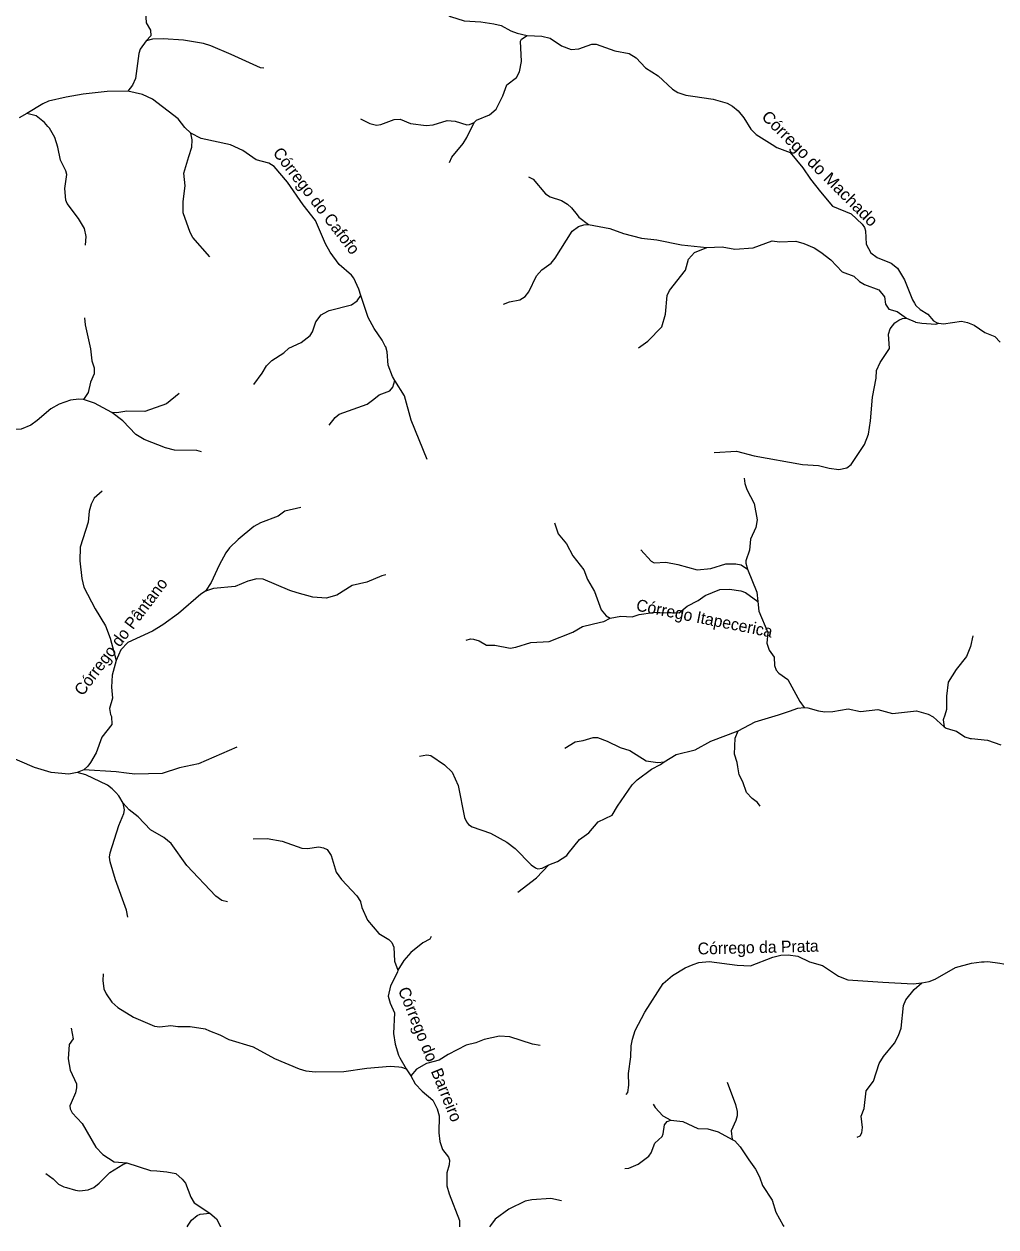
# Model space of a CAD drawing. Extents: x 473.9 to 500, y 7733.1 to 7760.8.
# Drawn here: x 480.86 to 487.45, y 7733.14 to 7741.31 of the extents above; entities that cross this region are included whole.
import ezdxf
from ezdxf.enums import TextEntityAlignment as Align

# ---------------------------------------------------------------- set-up
doc = ezdxf.new("R2010")
doc.units = 0
doc.header["$LTSCALE"] = 0.032
doc.layers.add('61', color=7, linetype='Continuous')
doc.layers.add('7', color=7, linetype='Continuous', lineweight=25)

msp = doc.modelspace()

# ---------------------------------------------------------------- linework, layer by layer
at = {"layer": '7'}
for p, q in [((480.8795, 7740.7), (480.8283, 7740.6712)), ((481.2664, 7736.2474), (481.2199, 7736.2289)), ((483.4526, 7734.2176), (483.4832, 7734.1696))]:
    msp.add_line(p, q, dxfattribs=at)
for points in [[(482.1099, 7741.7153), (481.984, 7741.7217), (481.7828, 7741.6667), (481.7217, 7741.6213), (481.6941, 7741.5852), (481.6778, 7741.5085), (481.6894, 7741.3158), (481.7178, 7741.266), (481.7194, 7741.228), (481.6886, 7741.1924)], [(482.7052, 7741.7027), (482.7719, 7741.7088), (482.8259, 7741.7005), (482.8866, 7741.6633), (482.9371, 7741.6172), (482.9774, 7741.6102), (483.0334, 7741.615), (483.0776, 7741.6118), (483.1055, 7741.6026), (483.2118, 7741.5318), (483.3296, 7741.4866), (483.4169, 7741.466), (483.5224, 7741.4723), (483.5616, 7741.4644), (483.6052, 7741.4474), (483.7526, 7741.3582), (483.8467, 7741.3279), (483.9579, 7741.3224), (484.0477, 7741.3087), (484.0961, 7741.2966), (484.1635, 7741.2601), (484.2055, 7741.2445), (484.2731, 7741.2289)], [(482.4876, 7741.0084), (482.4636, 7741.0099), (482.2663, 7741.1003), (482.1274, 7741.1594), (482.0783, 7741.1741), (481.941, 7741.1981), (481.805, 7741.2077), (481.7325, 7741.2046), (481.6886, 7741.1924)], [(483.9144, 7740.64), (483.9284, 7740.6552), (484.0168, 7740.6916), (484.062, 7740.7305), (484.1079, 7740.8197), (484.1358, 7740.8951), (484.2019, 7740.9445), (484.221, 7740.9835), (484.2337, 7741.0519), (484.2291, 7741.1908), (484.2343, 7741.204), (484.2731, 7741.2289)], [(484.2731, 7741.2289), (484.3717, 7741.2253), (484.4281, 7741.2108), (484.5059, 7741.1595), (484.5708, 7741.1347), (484.624, 7741.1386), (484.6806, 7741.1589), (484.7116, 7741.17), (484.7408, 7741.1708), (484.8676, 7741.1251), (484.9651, 7741.1072), (485.0115, 7741.0778), (485.0756, 7741.0091), (485.1609, 7740.9556), (485.2587, 7740.8657), (485.2956, 7740.842), (485.3486, 7740.825), (485.3963, 7740.8181), (485.5358, 7740.798), (485.6292, 7740.7706), (485.6666, 7740.7488), (485.7035, 7740.7184), (485.7432, 7740.6714), (485.7911, 7740.5939), (485.8265, 7740.5581), (485.9346, 7740.4899), (485.966, 7740.47), (486.058, 7740.4362), (486.1442, 7740.332), (486.1941, 7740.2536), (486.2639, 7740.1693), (486.345, 7740.0714), (486.4707, 7740.0195), (486.5467, 7739.95), (486.5622, 7739.9262), (486.5673, 7739.9032), (486.5718, 7739.8126), (486.6049, 7739.7556), (486.6485, 7739.7221), (486.7433, 7739.6851), (486.7864, 7739.6516), (486.8333, 7739.5702), (486.887, 7739.4355), (486.9016, 7739.4121), (486.9104, 7739.398), (486.9394, 7739.3699), (486.9903, 7739.338), (487.0298, 7739.2941), (487.0546, 7739.2788), (487.0664, 7739.277)], [(481.6886, 7741.1924), (481.649, 7741.1375), (481.6399, 7741.1076), (481.6155, 7740.9364), (481.5961, 7740.8921), (481.5647, 7740.8515)], [(481.5647, 7740.8515), (481.424, 7740.8501), (481.2605, 7740.8309), (481.1469, 7740.8108), (481.0269, 7740.7829), (480.9868, 7740.7661), (480.8795, 7740.7)], [(481.9912, 7740.5661), (481.9514, 7740.6046), (481.905, 7740.6628), (481.7327, 7740.7974), (481.6637, 7740.8297), (481.5647, 7740.8515)], [(481.2779, 7739.8059), (481.2824, 7739.8658), (481.2711, 7739.9192), (481.2297, 7739.9872), (481.153, 7740.09), (481.143, 7740.1122), (481.1374, 7740.1902), (481.1501, 7740.286), (481.1449, 7740.3107), (481.1067, 7740.3841), (481.0892, 7740.4717), (481.069, 7740.5361), (481.0324, 7740.6006), (481.0223, 7740.6121), (480.998, 7740.6399), (480.9426, 7740.6852), (480.8795, 7740.7)], [(483.1415, 7740.6643), (483.2049, 7740.631), (483.2514, 7740.6217), (483.2803, 7740.625), (483.372, 7740.6584), (483.4125, 7740.6609), (483.4814, 7740.6321), (483.5875, 7740.6177), (483.6346, 7740.6222), (483.7312, 7740.6521), (483.7845, 7740.6482), (483.8643, 7740.6241), (483.8816, 7740.6254), (483.9144, 7740.64)], [(483.7462, 7740.3678), (483.7625, 7740.4046), (483.8389, 7740.4968), (483.8649, 7740.5375), (483.9144, 7740.64)], [(482.1197, 7739.7264), (482.0047, 7739.8594), (481.9869, 7739.8919), (481.9408, 7740.0256), (481.9408, 7740.1036), (481.9543, 7740.2081), (481.944, 7740.296), (481.9787, 7740.408), (481.9984, 7740.4717), (482, 7740.5202), (481.9912, 7740.5661)], [(483.1438, 7739.4641), (483.1322, 7739.5087), (483.0964, 7739.5827), (483.0821, 7739.602), (482.9976, 7739.6749), (482.9359, 7739.7595), (482.9046, 7739.8156), (482.8385, 7739.9732), (482.7543, 7740.0799), (482.6474, 7740.235), (482.5575, 7740.3408), (482.5218, 7740.3638), (482.4347, 7740.3851), (482.3437, 7740.4494), (482.2617, 7740.4876), (482.0619, 7740.5312), (481.9912, 7740.5661)], [(484.2833, 7740.2699), (484.3149, 7740.254), (484.3975, 7740.1553), (484.4285, 7740.1355), (484.5058, 7740.1105), (484.5462, 7740.0858), (484.5733, 7740.0609), (484.6118, 7740.0113), (484.624, 7739.9956), (484.6882, 7739.9477)], [(484.1131, 7739.4056), (484.1536, 7739.4213), (484.2236, 7739.4349), (484.2586, 7739.4583), (484.2854, 7739.4897), (484.336, 7739.599), (484.3737, 7739.639), (484.4362, 7739.6855), (484.4627, 7739.7177), (484.579, 7739.9019), (484.6211, 7739.9321), (484.6572, 7739.9449), (484.6882, 7739.9477)], [(484.6882, 7739.9477), (484.8348, 7739.9201), (484.9256, 7739.8846), (485.0481, 7739.8536), (485.1539, 7739.8432), (485.3204, 7739.8095), (485.4912, 7739.7912)], [(485.4912, 7739.7912), (485.5952, 7739.7942), (485.6823, 7739.7798), (485.8073, 7739.7887), (485.9348, 7739.8351), (485.9842, 7739.8287), (486.0955, 7739.8335), (486.151, 7739.8177), (486.2193, 7739.7885), (486.2645, 7739.7593), (486.3339, 7739.7074), (486.4109, 7739.6265), (486.49, 7739.5969), (486.5286, 7739.5589), (486.5608, 7739.5391), (486.6586, 7739.5029), (486.6981, 7739.4556), (486.7032, 7739.4057), (486.7258, 7739.3733), (486.7823, 7739.356), (486.8467, 7739.3101)], [(485.0278, 7739.1088), (485.0922, 7739.1557), (485.1866, 7739.252), (485.2127, 7739.3393), (485.2224, 7739.4658), (485.2377, 7739.4991), (485.3482, 7739.6362), (485.3681, 7739.7109), (485.4087, 7739.7559), (485.4912, 7739.7912)], [(482.4187, 7738.8603), (482.4766, 7738.9371), (482.5061, 7738.9887), (482.5407, 7739.0241), (482.6217, 7739.0768), (482.6563, 7739.1084), (482.7406, 7739.147), (482.8002, 7739.1928), (482.8165, 7739.2183), (482.8395, 7739.2868), (482.875, 7739.3333), (482.9211, 7739.3591), (482.93, 7739.3641), (483.0814, 7739.4008), (483.1201, 7739.4278), (483.1438, 7739.4641)], [(483.3759, 7738.8891), (483.3594, 7738.9145), (483.3311, 7738.9926), (483.3229, 7739.083), (483.3136, 7739.1156), (483.3132, 7739.117), (483.29, 7739.1619), (483.2346, 7739.2401), (483.1948, 7739.3153), (483.1438, 7739.4641)], [(481.2694, 7739.3145), (481.2749, 7739.2651), (481.3121, 7739.1022), (481.3201, 7739.0224), (481.3353, 7738.974), (481.336, 7738.9338), (481.3105, 7738.8777), (481.296, 7738.8059), (481.2632, 7738.7589)], [(485.5417, 7738.3987), (485.693, 7738.4087), (485.8131, 7738.3763), (486.1412, 7738.3185), (486.2491, 7738.3118), (486.3208, 7738.2923), (486.3881, 7738.2838), (486.4406, 7738.295), (486.4712, 7738.3187), (486.5399, 7738.4194), (486.5607, 7738.4547), (486.5894, 7738.525), (486.6031, 7738.6136), (486.6168, 7738.7749), (486.6407, 7738.9031), (486.6439, 7738.956), (486.6672, 7739.0106), (486.7307, 7739.1053), (486.7249, 7739.203), (486.7352, 7739.2382), (486.7678, 7739.2804), (486.795, 7739.298), (486.8199, 7739.3092), (486.8467, 7739.3101)], [(486.8467, 7739.3101), (486.906, 7739.2854), (486.9076, 7739.2851), (486.9515, 7739.2763), (487.0448, 7739.2699), (487.0664, 7739.277)], [(487.0664, 7739.277), (487.098, 7739.2723), (487.2184, 7739.2898), (487.2592, 7739.2815), (487.306, 7739.2628), (487.3785, 7739.2133), (487.4447, 7739.1879), (487.482, 7739.1485)], [(482.9311, 7738.5847), (482.971, 7738.6372), (482.9983, 7738.6588), (483.188, 7738.7271), (483.2336, 7738.7626), (483.2691, 7738.7902), (483.3427, 7738.8191), (483.3627, 7738.8425), (483.3759, 7738.8891)], [(483.5943, 7738.3532), (483.4856, 7738.6199), (483.4416, 7738.7831), (483.3759, 7738.8891)], [(481.2632, 7738.7589), (481.2329, 7738.7623), (481.1758, 7738.7543), (481.0986, 7738.7269), (481.0411, 7738.6965), (480.9495, 7738.6162), (480.9062, 7738.5858), (480.8401, 7738.5582), (480.8046, 7738.5547), (480.7593, 7738.5622), (480.7158, 7738.581), (480.5023, 7738.7214), (480.4141, 7738.7696), (480.309, 7738.8145), (480.2236, 7738.8249), (480.1332, 7738.8067), (480.0869, 7738.7898)], [(481.4557, 7738.6714), (481.3393, 7738.735), (481.2632, 7738.7589)], [(481.9127, 7738.7999), (481.8271, 7738.7292), (481.6798, 7738.6779), (481.5568, 7738.6797), (481.4896, 7738.6678), (481.4557, 7738.6714)], [(482.0638, 7738.4052), (482.0323, 7738.4139), (481.8817, 7738.4148), (481.8191, 7738.4318), (481.6756, 7738.4888), (481.6197, 7738.522), (481.5308, 7738.6149), (481.4557, 7738.6714)], [(485.7445, 7738.2252), (485.7486, 7738.1885), (485.763, 7738.1484), (485.8127, 7738.0546), (485.8341, 7737.9436), (485.8252, 7737.8912), (485.7876, 7737.8119), (485.7804, 7737.7373), (485.7573, 7737.6645), (485.7563, 7737.648), (485.7677, 7737.6088)], [(481.3899, 7738.1362), (481.3359, 7738.0905), (481.3157, 7738.0497), (481.3025, 7738.0012), (481.2952, 7737.9269), (481.2401, 7737.7575), (481.2384, 7737.6637), (481.2512, 7737.5446), (481.2662, 7737.4865), (481.3428, 7737.3378), (481.413, 7737.224), (481.4435, 7737.1395), (481.4841, 7736.9874)], [(482.737, 7738.0255), (482.6289, 7738.0015), (482.5844, 7737.9681), (482.4648, 7737.9235), (482.4188, 7737.8966), (482.3117, 7737.8096), (482.2539, 7737.7533), (482.2295, 7737.7179), (482.1838, 7737.6355), (482.1302, 7737.5185), (482.0906, 7737.4577)], [(484.4577, 7737.9225), (484.4833, 7737.8482), (484.5392, 7737.7801), (484.5824, 7737.6996), (484.6571, 7737.6045), (484.6833, 7737.5376), (484.7304, 7737.4564), (484.7751, 7737.3317), (484.8085, 7737.2903), (484.8355, 7737.2761)], [(485.0433, 7737.7386), (485.1137, 7737.6619), (485.1348, 7737.6519), (485.2141, 7737.6551), (485.2953, 7737.6406), (485.4275, 7737.6046), (485.5185, 7737.6134), (485.6217, 7737.6437), (485.6895, 7737.6453), (485.7254, 7737.6373), (485.7677, 7737.6088)], [(483.3156, 7737.5695), (483.2874, 7737.5627), (483.1855, 7737.5191), (483.0867, 7737.4969), (482.982, 7737.4312), (482.9097, 7737.4114), (482.8197, 7737.4185), (482.7123, 7737.4466), (482.6631, 7737.4623), (482.4816, 7737.5396), (482.4405, 7737.542), (482.3779, 7737.526), (482.2914, 7737.4893), (482.1463, 7737.4778), (482.0906, 7737.4577)], [(485.7677, 7737.6088), (485.8313, 7737.4527), (485.8389, 7737.3882)], [(482.0906, 7737.4577), (482.0591, 7737.4379), (481.9073, 7737.308), (481.8013, 7737.2304), (481.7325, 7737.1862), (481.5644, 7737.1102), (481.5159, 7737.06), (481.4841, 7736.9874)], [(484.8355, 7737.2761), (484.9086, 7737.2886), (484.9863, 7737.2835), (485.0116, 7737.2929), (485.0327, 7737.3007), (485.1259, 7737.3143), (485.1322, 7737.3152), (485.1562, 7737.3148), (485.1737, 7737.3145), (485.3044, 7737.3124), (485.3577, 7737.357), (485.4338, 7737.3959), (485.4814, 7737.4289), (485.5806, 7737.4706), (485.6456, 7737.473), (485.7216, 7737.4619), (485.7549, 7737.4486), (485.8389, 7737.3882)], [(485.8389, 7737.3882), (485.8438, 7737.3223), (485.9047, 7737.1792), (485.9, 7737.1049), (485.9159, 7737.0585), (485.9477, 7737.0119), (485.9513, 7736.9539), (485.9616, 7736.9218), (485.9801, 7736.9015), (486.0415, 7736.8582), (486.1223, 7736.7107), (486.1523, 7736.669)], [(483.8601, 7737.1271), (483.8893, 7737.1357), (483.9095, 7737.134), (483.9486, 7737.1209), (483.9984, 7737.0917), (484.0529, 7737.0922), (484.1574, 7737.073), (484.196, 7737.0787), (484.2973, 7737.1097), (484.4233, 7737.1179), (484.584, 7737.18), (484.6478, 7737.2189), (484.7712, 7737.2475), (484.7936, 7737.2527), (484.8355, 7737.2761)], [(487.2974, 7737.1557), (487.2809, 7737.0837), (487.253, 7737.0153), (487.1828, 7736.9262), (487.1281, 7736.8403), (487.1179, 7736.7459), (487.1186, 7736.6553), (487.1064, 7736.618), (487.0962, 7736.5866), (487.1014, 7736.5389)], [(481.4841, 7736.9874), (481.4587, 7736.8883), (481.4533, 7736.8081), (481.4596, 7736.7316), (481.4403, 7736.6636), (481.4461, 7736.6219), (481.4533, 7736.6081), (481.4548, 7736.5543), (481.3876, 7736.4679), (481.3488, 7736.3615), (481.3117, 7736.295), (481.2926, 7736.2718), (481.2664, 7736.2474)], [(485.7051, 7736.511), (485.82, 7736.5718), (485.9775, 7736.6185), (486.0521, 7736.645), (486.1102, 7736.6657), (486.1523, 7736.669)], [(486.1523, 7736.669), (486.1768, 7736.6681), (486.2491, 7736.6457), (486.2932, 7736.6409), (486.3463, 7736.6425), (486.4515, 7736.6592), (486.535, 7736.6432), (486.6512, 7736.6553), (486.7507, 7736.6296), (486.9142, 7736.6473), (486.9932, 7736.6233), (487.0266, 7736.6051), (487.1014, 7736.5389)], [(485.2023, 7736.2996), (485.2841, 7736.3499), (485.4119, 7736.3814), (485.5188, 7736.4402), (485.7051, 7736.511)], [(485.8528, 7735.9995), (485.8367, 7736.0246), (485.7998, 7736.0521), (485.7613, 7736.093), (485.7363, 7736.1645), (485.7124, 7736.2124), (485.7029, 7736.2668), (485.6977, 7736.2962), (485.6787, 7736.3532), (485.6852, 7736.4617), (485.7051, 7736.511)], [(487.1014, 7736.5389), (487.1164, 7736.5289), (487.1601, 7736.5156), (487.1856, 7736.5079), (487.2423, 7736.4707), (487.2791, 7736.4593), (487.2884, 7736.4583), (487.3957, 7736.4468), (487.4861, 7736.4154)], [(481.2199, 7736.2289), (481.165, 7736.2178), (481.0453, 7736.2284), (480.9323, 7736.263), (480.6313, 7736.3904), (480.5739, 7736.4095), (480.5007, 7736.4163), (480.0508, 7736.286), (479.9923, 7736.2559), (479.9357, 7736.217), (479.8557, 7736.1355), (479.8278, 7736.1215), (479.7898, 7736.1148), (479.7604, 7736.1182)], [(482.303, 7736.4006), (482.0444, 7736.2865), (481.915, 7736.2591), (481.7963, 7736.2223), (481.611, 7736.2167), (481.5555, 7736.2234), (481.4842, 7736.2319), (481.2664, 7736.2474)], [(484.5276, 7736.3934), (484.5994, 7736.4371), (484.6525, 7736.4455), (484.7213, 7736.466), (484.7514, 7736.4661), (484.8161, 7736.4418), (484.9034, 7736.3981), (484.9692, 7736.3766), (485.0814, 7736.3075), (485.1585, 7736.2953), (485.2023, 7736.2996)], [(483.5429, 7736.3394), (483.5933, 7736.3473), (483.6196, 7736.3433), (483.7115, 7736.2797), (483.7639, 7736.2302), (483.8044, 7736.141), (483.849, 7735.9221), (483.8606, 7735.8941), (483.876, 7735.8754), (483.9005, 7735.8589), (484.024, 7735.8164), (484.1353, 7735.7552), (484.1907, 7735.7131), (484.2998, 7735.6026), (484.3307, 7735.582), (484.3351, 7735.5791), (484.3461, 7735.5753), (484.3742, 7735.5794), (484.4208, 7735.6023)], [(481.533, 7736.0209), (481.5038, 7736.0705), (481.4833, 7736.0918), (481.4583, 7736.1178), (481.4253, 7736.1425), (481.2802, 7736.2127), (481.2199, 7736.2289)], [(484.4208, 7735.6023), (484.4784, 7735.6246), (484.5414, 7735.6648), (484.5519, 7735.6781), (484.6272, 7735.773), (484.6919, 7735.8185), (484.7539, 7735.8941), (484.85, 7735.9381), (484.8865, 7736.0009), (484.9856, 7736.1443), (485.0201, 7736.1787), (485.1174, 7736.2517), (485.1787, 7736.2819), (485.2023, 7736.2996)], [(481.5633, 7735.2461), (481.5559, 7735.2952), (481.4803, 7735.4996), (481.4434, 7735.6215), (481.4396, 7735.6535), (481.4437, 7735.6841), (481.5044, 7735.8693), (481.5383, 7735.9499), (481.5414, 7735.976), (481.533, 7736.0209)], [(482.2413, 7735.3499), (482.2023, 7735.3599), (482.162, 7735.3902), (481.9647, 7735.5975), (481.8575, 7735.7458), (481.809, 7735.7865), (481.7192, 7735.8402), (481.6334, 7735.9274), (481.5731, 7735.9757), (481.533, 7736.0209)], [(482.4144, 7735.7773), (482.5099, 7735.7797), (482.6105, 7735.7614), (482.7443, 7735.7147), (482.7834, 7735.7116), (482.8601, 7735.7235), (482.8911, 7735.7173), (482.9155, 7735.7052), (482.9435, 7735.6653), (482.9768, 7735.5512), (483.0136, 7735.5023), (483.1185, 7735.3916), (483.1416, 7735.3518), (483.142, 7735.3503), (483.1512, 7735.312), (483.1912, 7735.2256), (483.2659, 7735.1369), (483.3345, 7735.0948), (483.356, 7735.0751), (483.3678, 7735.0436), (483.3742, 7734.9477), (483.3954, 7734.887)], [(484.2096, 7735.4164), (484.3365, 7735.5141), (484.4208, 7735.6023)], [(483.6231, 7735.1153), (483.6137, 7735.0979), (483.5654, 7735.0717), (483.4851, 7735.0061), (483.4374, 7734.952), (483.3954, 7734.887)], [(484.945, 7734.0443), (484.9552, 7734.0568), (484.9635, 7734.1076), (484.9611, 7734.1867), (484.9763, 7734.2983), (484.9798, 7734.3745), (484.9872, 7734.4188), (485.0066, 7734.4774), (485.0718, 7734.6029), (485.1957, 7734.7957), (485.2595, 7734.8501), (485.3453, 7734.9019), (485.3995, 7734.9249), (485.4384, 7734.9379), (485.5089, 7734.9457), (485.6982, 7734.9209), (485.7873, 7734.9153), (485.9404, 7734.9752), (485.9941, 7734.9877), (486.0446, 7734.9907), (486.109, 7734.9809), (486.1894, 7734.9426), (486.2769, 7734.9178), (486.386, 7734.8471), (486.4487, 7734.821), (486.6848, 7734.8063), (486.8917, 7734.7935), (486.9507, 7734.8002)], [(486.9507, 7734.8002), (487.0009, 7734.8109), (487.0403, 7734.8265), (487.1798, 7734.9042), (487.287, 7734.9346), (487.3547, 7734.9443), (487.374, 7734.9446), (487.3989, 7734.9451), (487.4798, 7734.9346), (487.5801, 7734.9154), (487.6953, 7734.8833), (487.7453, 7734.8897), (487.7738, 7734.9031), (487.87, 7734.9273), (487.9191, 7734.9282), (487.9548, 7734.9203)], [(481.3967, 7734.8619), (481.3937, 7734.8158), (481.4025, 7734.7605), (481.4175, 7734.7255), (481.4559, 7734.6697), (481.4975, 7734.6336), (481.6039, 7734.569), (481.7455, 7734.5068), (481.7812, 7734.5017), (481.8563, 7734.5113), (481.9027, 7734.5049), (481.9267, 7734.5049), (481.9876, 7734.5048), (482.0879, 7734.4881), (482.118, 7734.4764), (482.1886, 7734.449), (482.2495, 7734.4169), (482.4156, 7734.366), (482.5583, 7734.2866), (482.7258, 7734.2165), (482.7725, 7734.2031), (482.8376, 7734.197), (483.0306, 7734.2002), (483.185, 7734.2218), (483.3449, 7734.2355), (483.4018, 7734.2306), (483.4208, 7734.229), (483.4526, 7734.2176)], [(483.3954, 7734.887), (483.3936, 7734.8727), (483.346, 7734.7816), (483.3294, 7734.7098), (483.3431, 7734.6629), (483.3733, 7734.5969), (483.3662, 7734.4578), (483.3776, 7734.3856), (483.4006, 7734.3095), (483.4099, 7734.293), (483.4526, 7734.2176)], [(486.5126, 7733.7531), (486.5311, 7733.7627), (486.5445, 7733.7829), (486.5469, 7733.8204), (486.5385, 7733.8967), (486.5587, 7733.9481), (486.5738, 7734.0678), (486.6218, 7734.1334), (486.6607, 7734.2545), (486.6914, 7734.3015), (486.7647, 7734.3921), (486.7917, 7734.4429), (486.8107, 7734.4936), (486.826, 7734.6462), (486.8429, 7734.6863), (486.8979, 7734.7548), (486.9507, 7734.8002)], [(481.1792, 7734.4942), (481.1943, 7734.4206), (481.1665, 7734.3831), (481.1598, 7734.2852), (481.1739, 7734.2095), (481.2157, 7734.1167), (481.2167, 7734.0884), (481.2092, 7734.0536), (481.1795, 7733.9868), (481.1703, 7733.9661), (481.1728, 7733.9455), (481.1873, 7733.9186), (481.2557, 7733.8461), (481.3478, 7733.6865), (481.394, 7733.6365), (481.4721, 7733.587), (481.558, 7733.5791)], [(484.3605, 7734.376), (484.3088, 7734.3847), (484.1546, 7734.4352), (484.0859, 7734.4383), (483.9814, 7734.4156), (483.9253, 7734.3933), (483.8601, 7734.3783), (483.7373, 7734.3151), (483.6762, 7734.2754), (483.5905, 7734.2546), (483.5216, 7734.216), (483.4832, 7734.1696)], [(483.4832, 7734.1696), (483.5142, 7734.1164), (483.5608, 7734.0657), (483.6337, 7734.0056), (483.6633, 7733.9458), (483.6757, 7733.8987), (483.675, 7733.7821), (483.6807, 7733.7249), (483.6987, 7733.6705), (483.7396, 7733.6185), (483.7463, 7733.5988), (483.7447, 7733.5665), (483.7287, 7733.5125), (483.7291, 7733.4244), (483.7439, 7733.3691), (483.8149, 7733.1894), (483.8137, 7733.146)], [(485.6304, 7734.128), (485.687, 7733.9746), (485.6979, 7733.9272), (485.6979, 7733.8991), (485.6891, 7733.8669), (485.6578, 7733.7963), (485.6635, 7733.7382)], [(485.127, 7733.977), (485.1406, 7733.9544), (485.1941, 7733.8982), (485.2472, 7733.8702)], [(484.9353, 7733.5411), (484.9619, 7733.5437), (485.0264, 7733.5717), (485.0981, 7733.6245), (485.1152, 7733.6475), (485.1396, 7733.712), (485.1891, 7733.7591), (485.1968, 7733.7771), (485.2052, 7733.8378), (485.2219, 7733.8597), (485.2472, 7733.8702)], [(485.2472, 7733.8702), (485.3287, 7733.8611), (485.4306, 7733.8136), (485.4977, 7733.8097), (485.5684, 7733.7897), (485.6635, 7733.7382)], [(485.6635, 7733.7382), (485.6809, 7733.7288), (485.7174, 7733.6893), (485.7772, 7733.6009), (485.8212, 7733.5358), (485.8484, 7733.4845), (485.8704, 7733.4254), (485.935, 7733.3265), (485.9594, 7733.2442), (486.0098, 7733.1555), (486.0142, 7733.1477)], [(481.0086, 7733.5068), (481.0577, 7733.4715), (481.0935, 7733.4349), (481.1305, 7733.4175), (481.1489, 7733.4119), (481.2095, 7733.3936), (481.2361, 7733.3903), (481.2947, 7733.3954), (481.3327, 7733.4127), (481.3696, 7733.4408), (481.4429, 7733.5133), (481.53, 7733.569), (481.558, 7733.5791)], [(481.558, 7733.5791), (481.7175, 7733.5283), (481.76, 7733.5249), (481.83, 7733.5194), (481.8898, 7733.5067), (481.9339, 7733.4684), (481.9552, 7733.4406), (481.9919, 7733.3474), (482.0148, 7733.3086), (482.1212, 7733.2384)], [(484.5071, 7733.3224), (484.4344, 7733.3367), (484.3038, 7733.3294), (484.2597, 7733.3199), (484.1481, 7733.2656), (484.0572, 7733.1969), (484.0238, 7733.1539), (484.0178, 7733.1462)], [(481.9664, 7733.1446), (481.9738, 7733.1558), (481.9967, 7733.1905), (482.0337, 7733.2228), (482.0544, 7733.2317), (482.1212, 7733.2384)], [(482.1212, 7733.2384), (482.1654, 7733.2001), (482.1925, 7733.1475), (482.1939, 7733.1448)]]:
    msp.add_lwpolyline(points, dxfattribs=at)

# ---------------------------------------------------------------- texts
at = {"layer": '61', "width": 1.05}
msp.add_text('Córrego do Machado', height=0.08, rotation=315, dxfattribs=at).set_placement((486.2306, 7740.2988), align=Align.CENTER)
at = {"layer": '61'}
for s, rotation, p in [('Córrego do Cafofo', 307.629, (482.8126, 7740.0835)), ('Córrego do Pântano', 52.873, (481.5486, 7737.1268)), ('Córrego Itapecerica', 348.683, (485.4685, 7737.2357)), ('Córrego da Prata', 1.374, (485.8409, 7735.003)), ('Córrego do  Barreiro', 292.019, (483.5782, 7734.3014))]:
    msp.add_text(s, height=0.08, rotation=rotation, dxfattribs=at).set_placement(p, align=Align.CENTER)

doc.saveas('drawing.dxf')
